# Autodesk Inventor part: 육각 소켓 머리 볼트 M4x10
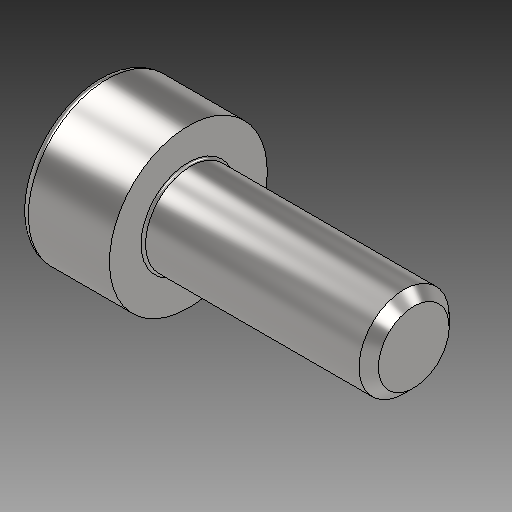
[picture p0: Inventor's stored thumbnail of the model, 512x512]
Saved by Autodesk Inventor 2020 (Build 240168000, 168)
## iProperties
Created: 2024-08
Part Number: 육각 소켓 머리 볼트 M4x10
Material: 강철, 연강
Description: 6각머리 태핑 나사
Document SubType Name: Modeling
Designer: 1강의실14
Density: 7.85 g/cm^3
Appearance: 기본값
Author: jhkim
Sending System: Autodesk Inventor 2025
Preprocessor: ST-DEVELOPER v20
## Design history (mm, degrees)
feature "Solid1"
node "솔리드1"
